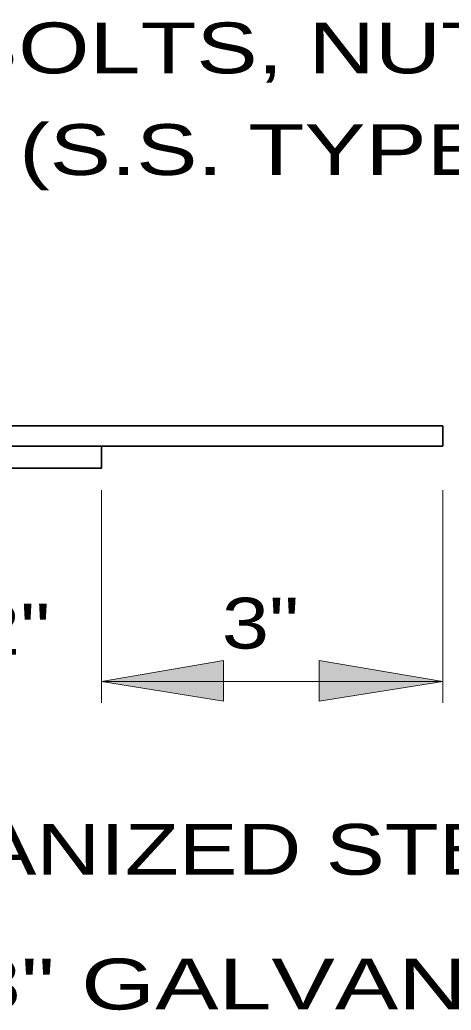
# Model space of a CAD drawing. Extents: x 5332.5 to 5339, y 1824.9 to 1835.1.
# Drawn here: x 5337.03 to 5337.54, y 1826.413 to 1827.582 of the extents above; entities that cross this region are included whole.
import ezdxf

# ---------------------------------------------------------------- set-up
doc = ezdxf.new("R2010")
doc.units = 0
doc.header["$LTSCALE"] = 0.024
for name, color, linetype, lineweight in [('1', 7, 'Continuous', 35), ('10', 7, 'Continuous', 13), ('12', 7, 'Continuous', 53)]:
    doc.layers.add(name, color=color, linetype=linetype, lineweight=lineweight)

msp = doc.modelspace()

# ---------------------------------------------------------------- hatches: boundary and pattern name
at = {"layer": '10'}
for points in [[(5337.271, 1826.778), (5337.271, 1826.826), (5337.127, 1826.801)], [(5337.271, 1826.778), (5337.271, 1826.826), (5337.127, 1826.801)], [(5337.271, 1826.778), (5337.271, 1826.826), (5337.127, 1826.801)], [(5337.271, 1826.778), (5337.271, 1826.826), (5337.127, 1826.801)], [(5337.271, 1826.778), (5337.271, 1826.826), (5337.127, 1826.801)], [(5337.271, 1826.778), (5337.271, 1826.826), (5337.127, 1826.801)], [(5337.271, 1826.778), (5337.271, 1826.826), (5337.127, 1826.801)], [(5337.271, 1826.778), (5337.271, 1826.826), (5337.127, 1826.801)], [(5337.271, 1826.778), (5337.271, 1826.826), (5337.127, 1826.801)], [(5337.271, 1826.778), (5337.271, 1826.826), (5337.127, 1826.801)], [(5337.271, 1826.778), (5337.271, 1826.826), (5337.127, 1826.801)], [(5337.384, 1826.778), (5337.384, 1826.826), (5337.53, 1826.801)], [(5337.384, 1826.778), (5337.384, 1826.826), (5337.53, 1826.801)], [(5337.384, 1826.778), (5337.384, 1826.826), (5337.53, 1826.801)], [(5337.384, 1826.778), (5337.384, 1826.826), (5337.53, 1826.801)], [(5337.384, 1826.778), (5337.384, 1826.826), (5337.53, 1826.801)], [(5337.384, 1826.778), (5337.384, 1826.826), (5337.53, 1826.801)], [(5337.384, 1826.778), (5337.384, 1826.826), (5337.53, 1826.801)], [(5337.384, 1826.778), (5337.384, 1826.826), (5337.53, 1826.801)], [(5337.384, 1826.778), (5337.384, 1826.826), (5337.53, 1826.801)], [(5337.384, 1826.778), (5337.384, 1826.826), (5337.53, 1826.801)], [(5337.384, 1826.778), (5337.384, 1826.826), (5337.53, 1826.801)]]:
    msp.add_hatch(color=256, dxfattribs=at).paths.add_polyline_path(points)

# ---------------------------------------------------------------- linework, layer by layer
at = {"layer": '1'}
for p, q in [((5337.53, 1827.103), (5333.857, 1827.103)), ((5337.53, 1827.079), (5337.53, 1827.103)), ((5337.53, 1827.079), (5337.53, 1827.103)), ((5337.53, 1827.079), (5337.53, 1827.103)), ((5337.53, 1827.079), (5337.53, 1827.103)), ((5337.53, 1827.079), (5337.53, 1827.103)), ((5337.53, 1827.079), (5337.53, 1827.103)), ((5337.53, 1827.079), (5337.53, 1827.103)), ((5337.53, 1827.079), (5337.53, 1827.103)), ((5337.53, 1827.079), (5337.53, 1827.103)), ((5337.53, 1827.079), (5337.53, 1827.103)), ((5337.53, 1827.079), (5337.53, 1827.103)), ((5337.53, 1827.079), (5337.53, 1827.103)), ((5337.53, 1827.079), (5337.53, 1827.103)), ((5335.895, 1827.079), (5337.127, 1827.079)), ((5335.895, 1827.079), (5337.127, 1827.079)), ((5335.895, 1827.079), (5337.127, 1827.079)), ((5335.895, 1827.079), (5337.127, 1827.079)), ((5335.895, 1827.079), (5337.127, 1827.079)), ((5335.895, 1827.079), (5337.127, 1827.079)), ((5335.895, 1827.079), (5337.127, 1827.079)), ((5335.895, 1827.079), (5337.127, 1827.079)), ((5335.895, 1827.079), (5337.127, 1827.079)), ((5335.895, 1827.079), (5337.127, 1827.079)), ((5335.895, 1827.079), (5337.127, 1827.079)), ((5335.895, 1827.079), (5337.127, 1827.079)), ((5335.895, 1827.079), (5337.127, 1827.079)), ((5337.127, 1827.079), (5337.53, 1827.079)), ((5337.127, 1827.079), (5337.53, 1827.079)), ((5337.127, 1827.079), (5337.53, 1827.079)), ((5337.127, 1827.079), (5337.53, 1827.079)), ((5337.127, 1827.079), (5337.53, 1827.079)), ((5337.127, 1827.079), (5337.53, 1827.079)), ((5337.127, 1827.079), (5337.53, 1827.079)), ((5337.127, 1827.079), (5337.53, 1827.079)), ((5337.127, 1827.079), (5337.53, 1827.079)), ((5337.127, 1827.079), (5337.53, 1827.079)), ((5337.127, 1827.079), (5337.53, 1827.079)), ((5337.127, 1827.079), (5337.53, 1827.079)), ((5337.127, 1827.079), (5337.53, 1827.079))]:
    msp.add_line(p, q, dxfattribs=at)
for points in [[(5337.53, 1827.103), (5333.857, 1827.103), (5333.857, 1827.079), (5334.26, 1827.079)], [(5337.53, 1827.103), (5333.857, 1827.103), (5333.857, 1827.079), (5334.26, 1827.079)], [(5337.53, 1827.103), (5333.857, 1827.103), (5333.857, 1827.079), (5334.26, 1827.079)], [(5337.53, 1827.103), (5333.857, 1827.103), (5333.857, 1827.079), (5334.26, 1827.079)], [(5337.53, 1827.103), (5333.857, 1827.103), (5333.857, 1827.079), (5334.26, 1827.079)], [(5337.53, 1827.103), (5333.857, 1827.103), (5333.857, 1827.079), (5334.26, 1827.079)], [(5337.53, 1827.103), (5333.857, 1827.103), (5333.857, 1827.079), (5334.26, 1827.079)], [(5337.53, 1827.103), (5333.857, 1827.103), (5333.857, 1827.079), (5334.26, 1827.079)], [(5337.53, 1827.103), (5333.857, 1827.103), (5333.857, 1827.079), (5334.26, 1827.079)], [(5337.53, 1827.103), (5333.857, 1827.103), (5333.857, 1827.079), (5334.26, 1827.079)], [(5337.53, 1827.103), (5333.857, 1827.103), (5333.857, 1827.079), (5334.26, 1827.079)], [(5337.53, 1827.103), (5333.857, 1827.103), (5333.857, 1827.079), (5334.26, 1827.079)], [(5337.53, 1827.103), (5333.857, 1827.103), (5333.857, 1827.079), (5334.26, 1827.079)], [(5335.922, 1827.053), (5337.127, 1827.053), (5337.127, 1827.079)], [(5335.922, 1827.053), (5337.127, 1827.053), (5337.127, 1827.079)], [(5335.922, 1827.053), (5337.127, 1827.053), (5337.127, 1827.079)], [(5335.922, 1827.053), (5337.127, 1827.053), (5337.127, 1827.079)], [(5335.922, 1827.053), (5337.127, 1827.053), (5337.127, 1827.079)], [(5335.922, 1827.053), (5337.127, 1827.053), (5337.127, 1827.079)], [(5335.922, 1827.053), (5337.127, 1827.053), (5337.127, 1827.079)], [(5335.922, 1827.053), (5337.127, 1827.053), (5337.127, 1827.079)], [(5335.922, 1827.053), (5337.127, 1827.053), (5337.127, 1827.079)], [(5335.922, 1827.053), (5337.127, 1827.053), (5337.127, 1827.079)], [(5335.922, 1827.053), (5337.127, 1827.053), (5337.127, 1827.079)], [(5335.922, 1827.053), (5337.127, 1827.053), (5337.127, 1827.079)], [(5335.922, 1827.053), (5337.127, 1827.053), (5337.127, 1827.079)]]:
    msp.add_lwpolyline(points, dxfattribs=at)
at = {"layer": '10'}
for p, q in [((5337.127, 1827.027), (5337.127, 1826.776)), ((5337.127, 1827.027), (5337.127, 1826.776)), ((5337.127, 1827.027), (5337.127, 1826.776)), ((5337.127, 1827.027), (5337.127, 1826.776)), ((5337.127, 1827.027), (5337.127, 1826.776)), ((5337.127, 1827.027), (5337.127, 1826.776)), ((5337.127, 1827.027), (5337.127, 1826.776)), ((5337.127, 1827.027), (5337.127, 1826.776)), ((5337.127, 1827.027), (5337.127, 1826.776)), ((5337.127, 1827.027), (5337.127, 1826.776)), ((5337.127, 1827.027), (5337.127, 1826.776)), ((5337.53, 1827.027), (5337.53, 1826.776)), ((5337.53, 1827.027), (5337.53, 1826.776)), ((5337.53, 1827.027), (5337.53, 1826.776)), ((5337.53, 1827.027), (5337.53, 1826.776)), ((5337.53, 1827.027), (5337.53, 1826.776)), ((5337.53, 1827.027), (5337.53, 1826.776)), ((5337.53, 1827.027), (5337.53, 1826.776)), ((5337.53, 1827.027), (5337.53, 1826.776)), ((5337.53, 1827.027), (5337.53, 1826.776)), ((5337.53, 1827.027), (5337.53, 1826.776)), ((5337.53, 1827.027), (5337.53, 1826.776)), ((5337.127, 1826.801), (5337.53, 1826.801)), ((5337.127, 1826.801), (5337.53, 1826.801)), ((5337.127, 1826.801), (5337.53, 1826.801)), ((5337.127, 1826.801), (5337.53, 1826.801)), ((5337.127, 1826.801), (5337.53, 1826.801)), ((5337.127, 1826.801), (5337.53, 1826.801)), ((5337.127, 1826.801), (5337.53, 1826.801)), ((5337.127, 1826.801), (5337.53, 1826.801)), ((5337.127, 1826.801), (5337.53, 1826.801)), ((5337.127, 1826.801), (5337.53, 1826.801)), ((5337.127, 1826.801), (5337.53, 1826.801))]:
    msp.add_line(p, q, dxfattribs=at)
for points in [[(5337.271, 1826.778), (5337.271, 1826.826), (5337.127, 1826.801)], [(5337.271, 1826.778), (5337.271, 1826.826), (5337.127, 1826.801)], [(5337.271, 1826.778), (5337.271, 1826.826), (5337.127, 1826.801)], [(5337.271, 1826.778), (5337.271, 1826.826), (5337.127, 1826.801)], [(5337.271, 1826.778), (5337.271, 1826.826), (5337.127, 1826.801)], [(5337.271, 1826.778), (5337.271, 1826.826), (5337.127, 1826.801)], [(5337.271, 1826.778), (5337.271, 1826.826), (5337.127, 1826.801)], [(5337.271, 1826.778), (5337.271, 1826.826), (5337.127, 1826.801)], [(5337.271, 1826.778), (5337.271, 1826.826), (5337.127, 1826.801)], [(5337.271, 1826.778), (5337.271, 1826.826), (5337.127, 1826.801)], [(5337.271, 1826.778), (5337.271, 1826.826), (5337.127, 1826.801)], [(5337.384, 1826.778), (5337.384, 1826.826), (5337.53, 1826.801)], [(5337.384, 1826.778), (5337.384, 1826.826), (5337.53, 1826.801)], [(5337.384, 1826.778), (5337.384, 1826.826), (5337.53, 1826.801)], [(5337.384, 1826.778), (5337.384, 1826.826), (5337.53, 1826.801)], [(5337.384, 1826.778), (5337.384, 1826.826), (5337.53, 1826.801)], [(5337.384, 1826.778), (5337.384, 1826.826), (5337.53, 1826.801)], [(5337.384, 1826.778), (5337.384, 1826.826), (5337.53, 1826.801)], [(5337.384, 1826.778), (5337.384, 1826.826), (5337.53, 1826.801)], [(5337.384, 1826.778), (5337.384, 1826.826), (5337.53, 1826.801)], [(5337.384, 1826.778), (5337.384, 1826.826), (5337.53, 1826.801)], [(5337.384, 1826.778), (5337.384, 1826.826), (5337.53, 1826.801)]]:
    msp.add_lwpolyline(points, close=True, dxfattribs=at)

# ---------------------------------------------------------------- texts
at = {"layer": '12'}
for s, width, p in [('1/4" x 1" BOLTS, NUTS AND', 1.35, (5336.524, 1827.519)), ('WASHER (S.S. TYPE 304)', 1.35, (5336.524, 1827.399)), ('2"', 1.25, (5336.975, 1826.833)), ('3"', 1.25, (5337.269, 1826.84)), ('3" x 1/4" GALVANIZED STEEL BAR', 1.3, (5336.286, 1826.573)), ('TS 6" x 4" x 3/8" GALVANIZED POST', 1.4, (5336.259, 1826.414))]:
    msp.add_text(s, height=0.06, dxfattribs=dict(at, width=width)).set_placement(p)

doc.saveas('drawing.dxf')
